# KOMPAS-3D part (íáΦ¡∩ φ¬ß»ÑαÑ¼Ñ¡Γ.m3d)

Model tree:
1. Эскиз:1
2. Смещенная плоскость:28
     Расстояние = 5.4
3. Смещенная плоскость:29
     Расстояние = 5.4
4. Смещенная плоскость:30
     Расстояние = 5.4
5. Смещенная плоскость:31
     Расстояние = 5.4
6. Смещенная плоскость:32
     Расстояние = 5.4
7. Смещенная плоскость:33
     Расстояние = 5.4
8. Смещенная плоскость:34
     Расстояние = 5.4
9. Эскиз:10
10. Эскиз:11
11. Эскиз:12
12. Эскиз:13
13. Эскиз:14
14. Эскиз:15
15. Эскиз:16
16. Поверхность по сечениям:12
     Толщина стенки 1 = 1; Толщина стенки 2 = 1
17. Заплатка:3
18. Сшивка поверхностей:6
     Точность сшивки = 0.01
19. Придать толщину:8
     Толщина стенки 1 = 1; Толщина стенки 2 = 1
20. Эскиз:43
21. Операция выдавливания:5
     Расстояние 1 = 13; Расстояние 2 = 5
22. Эскиз:44
23. Вырезать элемент выдавливания:11
     Расстояние 1 = 20
24. Скругление:6
     Радиус = 1
25. Скругление:8
     Радиус = 1
26. Эскиз:45
27. Вырезать элемент выдавливания:12
     Расстояние 2 = 20; Расстояние 1 = 20
28. Эскиз:46
29. Вырезать элемент выдавливания:13
     Расстояние 2 = 40; Расстояние 1 = 0.0231076
30. Скругление:9
     Радиус = 0.2

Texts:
  Сплав АЛ8  ГОСТ 1583-93
  stalker61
